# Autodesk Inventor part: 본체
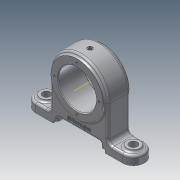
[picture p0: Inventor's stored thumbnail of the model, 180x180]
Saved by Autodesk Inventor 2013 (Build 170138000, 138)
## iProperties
Created: 2019-05
Part Number: 본체
Material: 알루미늄 6061
Document SubType Name: Modeling
Designer: user
Density: 2.71 g/cm^3
Mass: 456.712 g
Surface Area: 318.708 cm^2
Volume: 168.528 cm^3
Author: user
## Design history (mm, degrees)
sketch "스케치6"
  geometry: L1 (-40, 0)-(40, 0); L2 (40, 0)-(40, -60); L3 (40, -60)-(-40, -60); L4 (-40, -60)-(-40, 0); C1 r 40 at (0, 0); 2 further points
  constraints: 8 end point, 2 coincident, 2 parallel, 1 centre point, 1 horizontal, 1 midpoint, 1 perpendicular
  dimensions: "d30" = 80 diameter of C1; "d31" = 80 distance of L2.end L3.end; "d32" = 60 distance of L1.end L2.end
extrude "돌출6" new body sketch "스케치6" stored distance "d33" = 30; taper "d34" = 0 deg
sketch "스케치7"
  geometry: L1 (40, 0)-(100, 0); L2 (100, 0)-(100, -30); L3 (100, -30)-(40, -30); L4 (40, -30)-(40, 0); C1 r 15 at (100, -15); 3 further points
  constraints: 8 end point, 2 coincident, 2 midpoint, 2 parallel, 1 centre point, 1 horizontal, 1 perpendicular
  dimensions: "d35" = 30 diameter of C1; "d36" = 60 distance of L2.end L3.end; "d37" = 30 distance of L1.end L2.end
extrude "돌출7" join sketch "스케치7" distance "d38" = 12; taper "d39" = 0 deg
sketch "스케치8"
  geometry: C1 r 36 at (0, 0); A1 r 40 centre (0, 0) between (40, 0) and (-40, 0) reference
  constraints: 1 centre point, 1 coincident
  dimensions: "d40" = 72 diameter of C1
extrude "돌출8" join sketch "스케치8" distance "d41" = 3; taper "d42" = 0 deg
sketch "스케치9"
  geometry: C1 r 9 at (100, 15); A1 r 15 centre (100, 15) between (100, 0) and (100, 30) reference; 1 further point
  constraints: 1 centre point, 1 coincident
  dimensions: "d43" = 18 diameter of C1
extrude "돌출9" join sketch "스케치9" distance "d44" = 3; taper "d45" = 0 deg
sketch "스케치10"
  geometry: C1 r 9 at (0, 0) reference; C2 r 5.5 at (0, 0); 1 further point
  constraints: 1 centre point, 1 coincident
  dimensions: "d46" = 11 diameter of C2
extrude "돌출10" cut sketch "스케치10" stored distance "d47" = 3; taper "d48" = 0 deg
sketch "스케치11"
  geometry: C1 r 36 at (0, 0) reference; C2 r 26 at (0, 0)
  constraints: 1 centre point, 1 coincident
  dimensions: "d49" = 52 diameter of C2
extrude "돌출11" cut sketch "스케치11" stored distance "d50" = 3; taper "d51" = 0 deg
sketch "스케치12"
  geometry: L1 (60, -60)-(-60, -60) reference; L2 (-36, -60)-(-36, -56); L3 (-36, -56)-(-30, -56); L4 (-30, -56)-(-30, -50); L5 (-30, -50)-(30, -50); L6 (30, -50)-(30, -56); L7 (30, -56)-(36, -56); L8 (36, -56)-(36, -60); L9 (-36, -60)-(36, -60); L10 (0, -60)-(0, 0); A1 r 40 centre (0, 0) between (40, 0) and (-40, 0) reference
  constraints: 18 end point, 5 perpendicular, 3 parallel, 2 collinear, 2 point on line, 1 midpoint, 2 other
  dimensions: "d52" = 72 distance of L2.start L8.end; "d54" = 60 distance of L4.end L5.end; "d55" = 4 distance of L2.start L2.end; "d56" = 10 distance between parallel lines of L9 L5
extrude "돌출12" cut sketch "스케치12" stored distance "d57" = 3; taper "d58" = 0 deg
sketch "스케치13"
  geometry: L1 (0, 0)-(0, 31); C1 r 36 at (0, 0) reference; 1 further point
  constraints: 2 end point, 1 coincident, 1 vertical
  dimensions: "d59" = 31 distance of L1.start L1.end
hole "구멍1" sketch "스케치13" at (0, 31) diameter "d60" = 3.242; stored, may be unused: countersink angle "d64" = 90 deg, drill point angle "d66" = 118 deg; dims "d61" = 6, "d62" = 4, "d63" = 2, "d65" = 8
node "작업 평면1"
sketch "스케치14"
  geometry: 2 further points
  constraints: 1 coincident
hole "구멍2" sketch "스케치14" at (0, 0) diameter "d71" = 4.917; stored, may be unused: countersink angle "d75" = 90 deg, drill point angle "d77" = 118 deg; dims "d72" = 8, "d73" = 7, "d74" = 1, "d76" = 10
sketch "스케치15"
  geometry: L1 (-30, -50)-(30, -50) reference; A1 r 40 centre (0, 0) between (40, 0) and (-40, 0) reference; 1 further point
  constraints: 1 vertical alignment, 1 other
  dimensions: "d78" = 7 distance from line of L1 point (0, -43)
feature "엠보싱1" sketch "스케치15" dims "d79" = 0.5, "d80" = 0
fillet "모깎기1" dims "d81" = 6
fillet "모깎기2" dims "d82" = 3
chamfer "모따기1" distance "d83" = 1; stored, may be unused: second distance "d84" = 2, angle "d85" = 45 deg
fillet "모깎기3" dims "d86" = 3
fillet "모깎기4" dims "d87" = 3
fillet "모깎기5" dims "d88" = 3
fillet "모깎기6" dims "d89" = 3
sketch "스케치16"
  geometry: C1 r 1.5 at (0, 26); 1 further point
  constraints: 1 centre point, 1 vertical alignment, 1 other
  dimensions: "d90" = 3 diameter of C1
extrude "돌출13" cut sketch "스케치16" stored distance "d91" = 3; taper "d92" = 0 deg
node "작업 평면2"
sketch "스케치17"
  geometry: C1 r 1 at (0, 0); 1 further point
  constraints: 1 centre point, 1 coincident
  dimensions: "d94" = 2 diameter of C1
extrude "돌출14" cut sketch "스케치17" stored distance "d95" = 3; taper "d96" = 0 deg
node "솔리드2"
mirror "대칭2"
mirror "대칭3"
mirror "대칭4"
mirror "대칭5"
pattern_circular "원형 패턴1" dims angle "d68" = 360 deg
mirror "대칭6"
node "작업축1"
